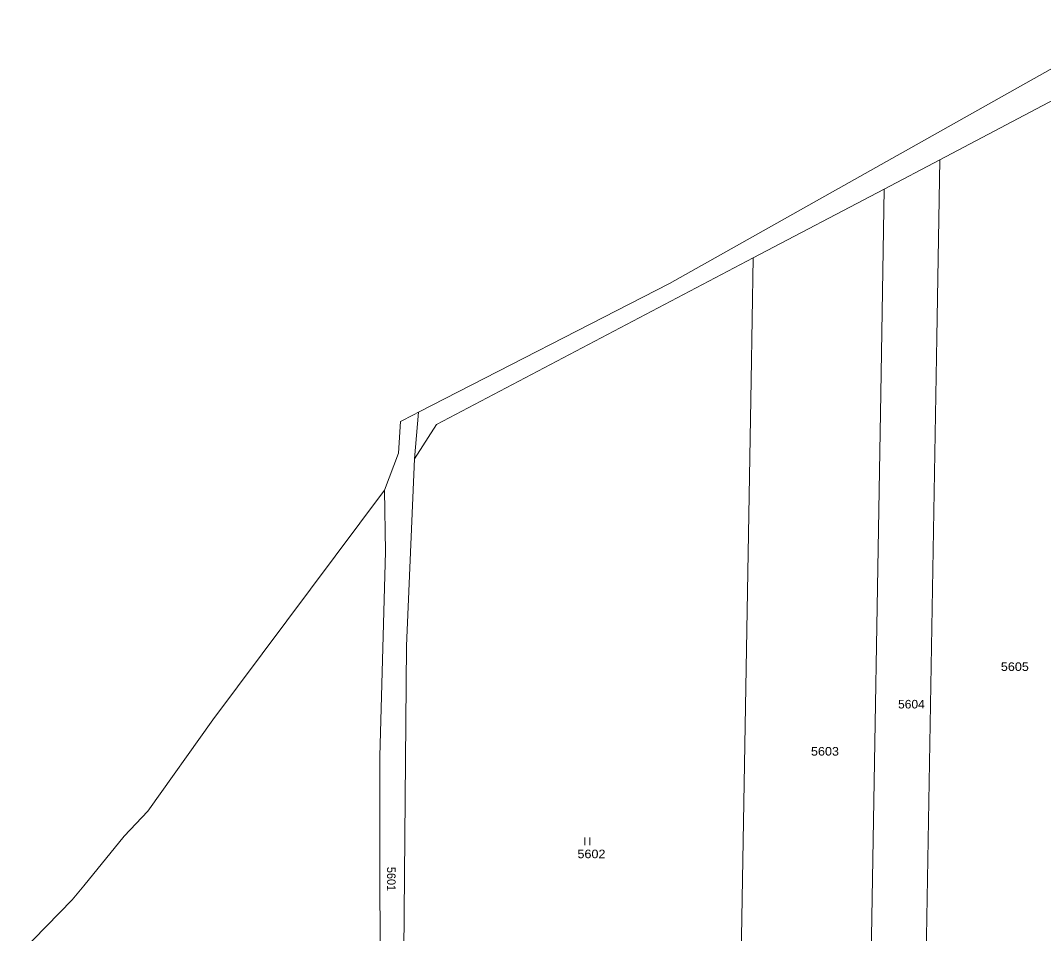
# Model space of a CAD drawing. Extents: x -590528 to -586543, y -1119609 to -1116685.
# Drawn here: x -588967.9 to -588764.7, y -1117923.1 to -1117741.8 of the extents above; entities that cross this region are included whole.
import ezdxf

# ---------------------------------------------------------------- set-up
doc = ezdxf.new("R2010")
doc.units = 0
doc.header["$LTSCALE"] = 0.68
for name, color, linetype, lineweight in [('1', 7, 'Continuous', 13), ('3', 7, 'Continuous', 13), ('6', 7, 'Continuous', 13)]:
    doc.layers.add(name, color=color, linetype=linetype, lineweight=lineweight)

msp = doc.modelspace()

# ---------------------------------------------------------------- linework, layer by layer
at = {"layer": '1'}
for p, q in [((-588746.16, -1117741.76), (-588839.01, -1117793.97)), ((-588785.91, -1117804.73), (-588785.3, -1117769.43)), ((-588822.39, -1117788.91), (-588796.35, -1117775.23)), ((-588797.05, -1117815.84), (-588796.35, -1117775.23)), ((-588822.81, -1117813.26), (-588822.39, -1117788.91)), ((-588839.01, -1117793.97), (-588888.89, -1117819.58)), ((-588789.02, -1117984.7), (-588785.91, -1117804.73)), ((-588826, -1117998.2), (-588822.81, -1117813.26)), ((-588800.03, -1117988.72), (-588797.05, -1117815.84)), ((-588889.63, -1117828.79), (-588888.89, -1117819.58)), ((-588929.74, -1117880.64), (-588895.58, -1117835.03)), ((-588895.58, -1117835.03), (-588895.38, -1117847.24)), ((-588942.62, -1117898.76), (-588929.74, -1117880.64)), ((-588947.29, -1117903.77), (-588942.62, -1117898.76)), ((-588967.92, -1117926.89), (-588957.66, -1117916.42))]:
    msp.add_line(p, q, dxfattribs=at)
for points in [[(-588796.35, -1117775.23), (-588785.3, -1117769.43), (-588758.92, -1117755.56)], [(-588892.52, -1118010.27), (-588891.23, -1117865.97), (-588889.63, -1117828.79), (-588885.3, -1117821.98), (-588822.39, -1117788.91)], [(-588888.89, -1117819.58), (-588889.86, -1117820.08), (-588892.45, -1117821.41), (-588892.84, -1117827.68), (-588895.58, -1117835.03)], [(-588895.38, -1117847.24), (-588896.51, -1117887.9), (-588896.48, -1117949.18)], [(-588957.66, -1117916.42), (-588955.3, -1117913.6), (-588947.29, -1117903.77)]]:
    msp.add_lwpolyline(points, dxfattribs=at)
at = {"layer": '6'}
for p, q in [((-588855.85, -1117905.53), (-588855.85, -1117904.03)), ((-588854.85, -1117905.53), (-588854.85, -1117904.03))]:
    msp.add_line(p, q, dxfattribs=at)

# ---------------------------------------------------------------- texts
at = {"layer": '3'}
for s, width, p in [('5605', 1.1, (-588773.183, -1117870.94)), ('5604', 1.05, (-588793.603, -1117878.39)), ('5603', 1.1, (-588810.903, -1117887.75)), ('5602', 1.1, (-588857.283, -1117908.13))]:
    msp.add_text(s, height=1.7, dxfattribs=dict(at, width=width)).set_placement(p)
at = {"layer": '3', "width": 0.95}
msp.add_text('5601', height=1.7, rotation=270.608, dxfattribs=at).set_placement((-588895.127, -1117909.867))

doc.saveas('drawing.dxf')
